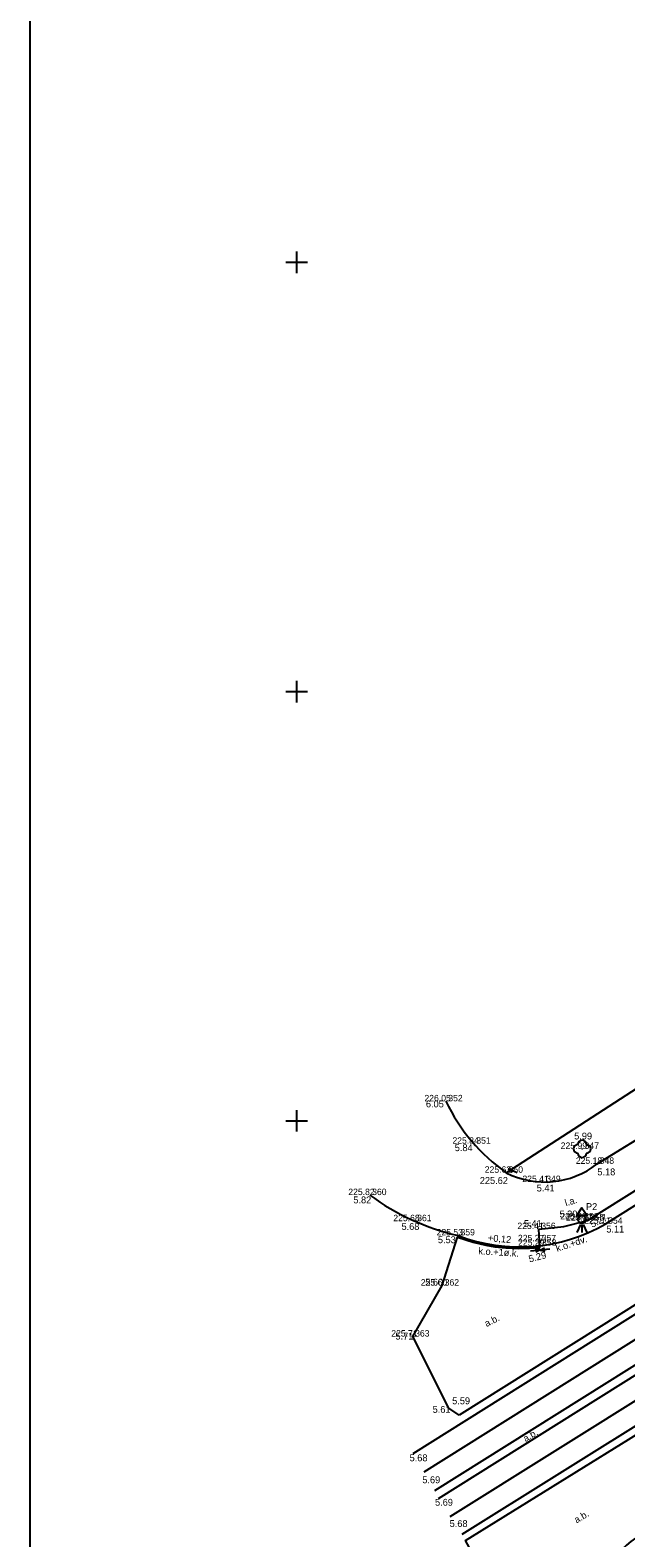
# Model space of a CAD drawing. Extents: x -598741 to -598592, y -1156973 to -1156763.
# Drawn here: x -598740.5 to -598705.9, y -1156924.3 to -1156836.5 of the extents above; entities that cross this region are included whole.
import ezdxf

# ---------------------------------------------------------------- set-up
doc = ezdxf.new("R2010")
doc.units = 0
for name, color, linetype in [('Vrstva 1', 7, 'Continuous'), ('Vrstva 10', 7, 'Continuous'), ('Vrstva 13', 7, 'Continuous'), ('Vrstva 14', 7, 'Continuous'), ('Vrstva 17', 7, 'Continuous'), ('Vrstva 19', 7, 'Continuous'), ('Vrstva 2', 7, 'Continuous'), ('Vrstva 3', 7, 'Continuous'), ('Vrstva 44', 7, 'Continuous'), ('Vrstva 49', 7, 'Continuous'), ('Vrstva 50', 7, 'Continuous'), ('Vrstva 58', 7, 'Continuous'), ('Vrstva 61', 7, 'Continuous'), ('Vrstva 62', 7, 'Continuous'), ('Vrstva 63', 7, 'Continuous'), ('Vrstva 7', 7, 'Continuous')]:
    doc.layers.add(name, color=color, linetype=linetype)

msp = doc.modelspace()

# ---------------------------------------------------------------- linework, layer by layer
at = {"layer": 'Vrstva 1'}
for p, q in [((-598716.32, -1156898.86), (-598716.32, -1156898.86)), ((-598714.69, -1156901.33), (-598714.69, -1156901.33)), ((-598708.39, -1156901.63), (-598708.39, -1156901.63)), ((-598707.51, -1156902.5), (-598707.51, -1156902.5)), ((-598712.81, -1156903.02), (-598712.81, -1156903.02)), ((-598720.75, -1156904.32), (-598720.75, -1156904.32)), ((-598710.62, -1156903.56), (-598710.62, -1156903.56)), ((-598718.13, -1156905.84), (-598718.13, -1156905.84)), ((-598708.41, -1156905.74), (-598708.41, -1156905.74)), ((-598708.08, -1156905.8), (-598708.08, -1156905.8)), ((-598707.02, -1156905.99), (-598707.02, -1156905.99)), ((-598715.61, -1156906.67), (-598715.61, -1156906.67)), ((-598710.91, -1156906.3), (-598710.91, -1156906.3)), ((-598710.88, -1156907.01), (-598710.88, -1156907.01)), ((-598710.87, -1156907.27), (-598710.87, -1156907.27)), ((-598716.53, -1156909.59), (-598716.53, -1156909.59)), ((-598718.25, -1156912.56), (-598718.25, -1156912.56))]:
    msp.add_line(p, q, dxfattribs=at)
at = {"layer": 'Vrstva 10'}
msp.add_line((-598712.81, -1156903.02), (-598694.89, -1156891.42), dxfattribs=at)
msp.add_arc((-598706.594, -1156894.214), 10.779, 205.5311, 234.7809, dxfattribs=at)
at = {"layer": 'Vrstva 13'}
for p, q in [((-598716.756, -1156921.986), (-598657.165, -1156884.63)), ((-598715.375, -1156924.074), (-598655.724, -1156886.71))]:
    msp.add_line(p, q, dxfattribs=at)
for points in [[(-598665.789, -1156886.262), (-598678.488, -1156894.428), (-598718.236, -1156919.397)], [(-598716.964, -1156921.524), (-598677.173, -1156896.562), (-598664.321, -1156888.348)]]:
    msp.add_lwpolyline(points, dxfattribs=at)
at = {"layer": 'Vrstva 14'}
msp.add_circle((-598708.39, -1156901.63), 0.00025, dxfattribs=at)
for centre, start, end in [((-598708.64, -1156901.63), 89.99999, 269.99999), ((-598708.39, -1156901.38), 0, 179.99999), ((-598708.14, -1156901.63), 270, 89.99999), ((-598708.39, -1156901.88), 179.99999, 359.99999)]:
    msp.add_arc(centre, 0.25, start, end, dxfattribs=at)
at = {"layer": 'Vrstva 17'}
msp.add_line((-598707.51, -1156902.5), (-598696.01, -1156895.4), dxfattribs=at)
msp.add_arc((-598710.565, -1156898.628), 4.932, 242.93116, 308.27592, dxfattribs=at)
at = {"layer": 'Vrstva 19'}
msp.add_line((-598716.065, -1156923.03), (-598656.445, -1156885.67), dxfattribs=at)
msp.add_lwpolyline([(-598665.055, -1156887.305), (-598677.83, -1156895.495), (-598717.6, -1156920.46)], dxfattribs=at)
at = {"layer": 'Vrstva 44'}
for p, q in [((-598708.485, -1156906.04), (-598708.71, -1156906.49)), ((-598708.41, -1156906.04), (-598708.41, -1156906.49)), ((-598708.335, -1156906.04), (-598708.11, -1156906.49))]:
    msp.add_line(p, q, dxfattribs=at)
msp.add_lwpolyline([(-598708.107, -1156905.516), (-598708.709, -1156905.516), (-598708.41, -1156905.059)], close=True, dxfattribs=at)
msp.add_circle((-598708.41, -1156905.74), 0.224, dxfattribs=at)
at = {"layer": 'Vrstva 49'}
for p, q in [((-598712.18, -1156903.016), (-598712.701, -1156902.798)), ((-598712.701, -1156902.798), (-598712.491, -1156902.988)), ((-598712.701, -1156902.798), (-598712.419, -1156902.81)), ((-598711.399, -1156907.566), (-598710.837, -1156907.515)), ((-598710.837, -1156907.515), (-598711.111, -1156907.446)), ((-598710.837, -1156907.515), (-598711.092, -1156907.637)), ((-598710.844, -1156907.521), (-598710.589, -1156907.399)), ((-598710.282, -1156907.47), (-598710.844, -1156907.521)), ((-598710.844, -1156907.521), (-598710.57, -1156907.59))]:
    msp.add_line(p, q, dxfattribs=at)
at = {"layer": 'Vrstva 61'}
msp.add_lwpolyline([(-598740.51, -1156762.629), (-598592.01, -1156762.63), (-598592.01, -1156972.63), (-598740.511, -1156972.63)], close=True, dxfattribs=at)
at = {"layer": 'Vrstva 62'}
for p, q in [((-598725, -1156850.625), (-598725, -1156849.375)), ((-598725.625, -1156850), (-598724.375, -1156850)), ((-598725, -1156875.625), (-598725, -1156874.375)), ((-598725.625, -1156875), (-598724.375, -1156875)), ((-598725, -1156900.625), (-598725, -1156899.375)), ((-598725.625, -1156900), (-598724.375, -1156900))]:
    msp.add_line(p, q, dxfattribs=at)
at = {"layer": 'Vrstva 63'}
for points in [[(-598715.55, -1156917.14), (-598716.14, -1156916.73), (-598718.25, -1156912.56), (-598716.53, -1156909.59), (-598715.646, -1156906.763), (-598714.74, -1156907.06), (-598714, -1156907.24), (-598713.47, -1156907.33), (-598712.83, -1156907.4), (-598712.11, -1156907.44), (-598711.46, -1156907.42), (-598710.86, -1156907.37), (-598710.87, -1156907.27), (-598710.88, -1156907.01), (-598710.91, -1156906.3), (-598709.45, -1156906.15), (-598708.08, -1156905.8), (-598661.52, -1156876.57)], [(-598639.97, -1156884.56), (-598642.51, -1156885.7), (-598649.28, -1156889.83), (-598648.88, -1156890.41), (-598665.92, -1156901.18), (-598683.74, -1156912.35), (-598699.88, -1156922.5), (-598701.13, -1156922.47), (-598704.74, -1156924.93), (-598706.51, -1156926.67), (-598708.08, -1156929.03), (-598708.58, -1156930.282), (-598709.09, -1156932.3), (-598709.75, -1156932.17), (-598711.17, -1156931.77), (-598715.18, -1156924.43), (-598699.21, -1156914.53), (-598663.81, -1156892.35), (-598655, -1156886.83)], [(-598702.24, -1156908.79), (-598715.55, -1156917.14)]]:
    msp.add_lwpolyline(points, dxfattribs=at)
at = {"layer": 'Vrstva 7'}
msp.add_lwpolyline([(-598658.54, -1156875.17), (-598661.27, -1156877.23), (-598674.96, -1156885.84), (-598707.02, -1156905.99)], dxfattribs=at)
for centre, radius, start, end in [((-598712.599, -1156893.289), 13.715, 233.53999, 257.32039), ((-598712.024, -1156897.367), 9.97, 248.92165, 300.13075), ((-598698.287, -1156933.456), 11.535, 120.72192, 173.59983)]:
    msp.add_arc(centre, radius, start, end, dxfattribs=at)

# ---------------------------------------------------------------- texts
at = {"layer": 'Vrstva 2'}
for s, p in [(' 352', (-598716.32, -1156898.86)), (' 351', (-598714.69, -1156901.33)), (' 347', (-598708.39, -1156901.63)), (' 348', (-598707.51, -1156902.5)), (' 350', (-598712.81, -1156903.02)), (' 349', (-598710.62, -1156903.56)), (' 360', (-598720.75, -1156904.32)), (' 361', (-598718.13, -1156905.84)), (' 356', (-598710.91, -1156906.3)), (' 353', (-598708.41, -1156905.74)), (' 355', (-598708.08, -1156905.8)), (' 354', (-598707.02, -1156905.99)), (' 359', (-598715.61, -1156906.67)), (' 357', (-598710.88, -1156907.01)), (' 358', (-598710.87, -1156907.27)), (' 362', (-598716.53, -1156909.59)), (' 363', (-598718.25, -1156912.56))]:
    msp.add_text(s, height=0.375, dxfattribs=at).set_placement(p)
at = {"layer": 'Vrstva 3'}
for s, p in [('226.05 ', (-598717.57, -1156898.86)), ('225.84 ', (-598715.94, -1156901.33)), ('225.99 ', (-598709.64, -1156901.63)), ('225.18 ', (-598708.76, -1156902.5)), ('225.62 ', (-598714.06, -1156903.02)), ('225.41 ', (-598711.87, -1156903.56)), ('225.82 ', (-598722, -1156904.32)), ('225.68 ', (-598719.38, -1156905.84)), ('225.41 ', (-598712.16, -1156906.3)), ('225.30 ', (-598709.66, -1156905.74)), ('225.27 ', (-598709.33, -1156905.8)), ('225.11 ', (-598708.27, -1156905.99)), ('225.53 ', (-598716.86, -1156906.67)), ('225.27 ', (-598712.13, -1156907.01)), ('225.29 ', (-598712.12, -1156907.27)), ('225.60 ', (-598717.78, -1156909.59)), ('225.71 ', (-598719.5, -1156912.56))]:
    msp.add_text(s, height=0.375, dxfattribs=at).set_placement(p)
at = {"layer": 'Vrstva 49'}
for s, rotation, p in [('l.a.', 17.41797, (-598709.329, -1156904.975)), ('k.o.+dv.', 18.15117, (-598709.846, -1156907.629)), ('k.o.+1ø.k.', 356.20674, (-598714.437, -1156907.763)), ('a.b.', 27.08355, (-598713.949, -1156912.008)), ('a.b.', 30.72469, (-598711.687, -1156918.709)), ('a.b.', 30.69368, (-598708.717, -1156923.447))]:
    msp.add_text(s, height=0.4, rotation=rotation, dxfattribs=at).set_placement(p)
msp.add_text('P2', height=0.4, dxfattribs=at).set_placement((-598708.17, -1156905.19))
at = {"layer": 'Vrstva 50'}
msp.add_text('+0,12', height=0.4, rotation=354.88521, dxfattribs=at).set_placement((-598713.886, -1156906.998))
at = {"layer": 'Vrstva 58'}
for s, p in [('6.05', (-598717.483, -1156899.21)), ('5.99', (-598708.856, -1156901.08)), ('5.84', (-598715.806, -1156901.76)), ('225.62', (-598714.348, -1156903.67)), ('5.18', (-598707.506, -1156903.17)), ('5.41', (-598711.036, -1156904.11)), ('5.82', (-598721.706, -1156904.8)), ('5.30', (-598709.71, -1156905.62)), ('5.68', (-598718.903, -1156906.35)), ('5.41', (-598711.786, -1156906.18)), ('5.11', (-598706.985, -1156906.5)), ('5.53', (-598716.786, -1156907.12)), ('5.60', (-598717.523, -1156909.59)), ('5.71', (-598719.256, -1156912.73)), ('5.61', (-598717.092, -1156917)), ('5.59', (-598715.956, -1156916.5)), ('5.68', (-598718.433, -1156919.82)), ('5.69', (-598717.693, -1156921.1)), ('5.69', (-598716.953, -1156922.41)), ('5.68', (-598716.103, -1156923.65))]:
    msp.add_text(s, height=0.4, dxfattribs=at).set_placement(p)
for s, rotation, p in [('5.27', 26.56505, (-598707.799, -1156906.232)), ('5.29', 14.57422, (-598711.448, -1156908.245))]:
    msp.add_text(s, height=0.4, rotation=rotation, dxfattribs=at).set_placement(p)

doc.saveas('drawing.dxf')
